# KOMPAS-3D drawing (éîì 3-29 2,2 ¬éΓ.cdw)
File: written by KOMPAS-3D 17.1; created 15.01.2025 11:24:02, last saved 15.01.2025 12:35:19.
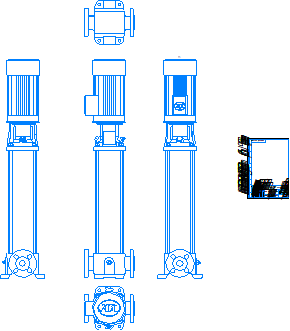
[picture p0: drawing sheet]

Sheet 1: A4, portrait

Title block, sheet 1: name: ВМН 3-29 2,2 кВт; designation: ВМН 3-29 2,2 кВт; material: Сталь 10  ГОСТ 1050-2013; mass: 68,16; sheets: 1; sheet format: A4; stored path: \\adlc.lan\data\АДЛ_ПКД\3D-модели\ADL production\Насосы ГРАНПАМП\Насосы ВМН\ВМН3\KOMPAS 3D\ВМН 3-29 2,2 кВт.cdw

Views: Проекционный вид 2, Проекционный вид 3, Проекционный вид 4, Проекционный вид 5
Referenced files in \\adlc.lan\data\АДЛ_ПКД\3D-модели\ADL production\Насосы ГРАНПАМП\Насосы ВМН\ВМН3\KOMPAS 3D\: ВМН 3-29 2,2 кВт.m3d
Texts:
  Andrey
  АДЛ
Dimensions and other numbers on the sheet: 1:1; 1; 68,16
